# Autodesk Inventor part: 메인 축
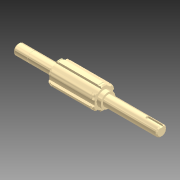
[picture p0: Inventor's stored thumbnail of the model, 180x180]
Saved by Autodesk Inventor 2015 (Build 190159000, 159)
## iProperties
Created: 2012-05
Part Number: 메인 축
Document SubType Name: 모델링
Designer: SeoGD™
Mass: 168.352 g
Surface Area: 72.5104 cm^2
Volume: 21.4461 cm^3
Density: 7.85 g/cm^3
Material: 강철, 연강
Appearance: 반연마
변환 표준: STEP AP214IS
파일 이름: C:\Users\SeoGD\Desktop\?쒗뿕\硫붿씤 異?.stp
전처리기: Build: 253, Release: 2010 SP1 - Date: Wed 07/29/2009
전송 단위: 밀리미터
불확실성: 0.01
Author: SeoGD™
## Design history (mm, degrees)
sketch "스케치1"
  geometry: L1 (-69.5, 0)-(69.5, 0); L2 (69.5, 0)-(69.5, 5); L3 (69.5, 5)-(55.5, 5); L4 (55.5, 5)-(55.5, 4.8); L5 (55.5, 4.8)-(54.35, 4.8); L6 (54.35, 4.8)-(54.35, 5); L7 (54.35, 5)-(30.5, 5); L8 (30.5, 5)-(30.5, 9); L9 (30.5, 9)-(-13.5, 9); L10 (-13.5, 9)-(-13.5, 7); L11 (-13.5, 7)-(-17.5, 7); L12 (-17.5, 7)-(-17.5, 5); L13 (-17.5, 5)-(-69.5, 5); L14 (-69.5, 5)-(-69.5, 0); 2 further points
  constraints: 28 end point, 9 parallel, 4 collinear, 2 perpendicular, 1 coincident, 1 horizontal, 1 midpoint
  dimensions: "d2" = 1.15 distance between parallel lines of L6 L4; "d3" = 10 diameter of L3 L1; "d4" = 9.6 diameter of L5 L1; "d6" = 44 distance between parallel lines of L10 L8; "d7" = 4 distance between parallel lines of L12 L10; "d8" = 14 diameter of L11 L1; "d9" = 18 diameter of L9 L1; "d33" = 52 distance from line of L12.end L14; "d37" = 39 distance between parallel lines of L8 L2; "d38" = 14 distance between parallel lines of L2 L4
revolve "회전1" sketch "스케치1" stored, may be unused: angle "d10" = 90 deg
sketch "스케치2"
  geometry: L1 (2.5, 10.712)-(2.5, 8.646); L2 (-2.5, 10.712)-(-2.5, 8.646); A1 r 9 centre (0, 0) between (2.5, 8.646) and (-2.5, 8.646) reference; A2 r 11 centre (0, 0) between (2.5, 10.712) and (-2.5, 10.712); 1 further point
  constraints: 4 end point, 4 point on circle, 2 parallel, 1 centre point, 1 coincident, 1 vertical
  dimensions: "d11" = 22 diameter of A2; "d12" = 5 distance between parallel lines of L1 L2
extrude "돌출1" join sketch "스케치2" stored distance "d13" = 10; taper "d14" = 0 deg
chamfer "모따기1" distance "d15" = 1; stored, may be unused: second distance "d16" = 2, angle "d17" = 45 deg
node "작업 평면1"
node "작업 평면2"
sketch "스케치3"
  geometry: L1 (2.5, 10.712)-(2.5, 10.198); L2 (-2.5, 10.712)-(-2.5, 10.198); A1 r 11 centre (0, 0) between (2.5, 10.712) and (-2.5, 10.712) reference; A2 r 10.5 centre (0, 0) between (2.5, 10.198) and (-2.5, 10.198); 1 further point
  constraints: 4 end point, 2 point on circle, 1 centre point, 1 coincident, 1 parallel, 1 vertical
  dimensions: "d19" = 21 diameter of A2
extrude "돌출2" cut sketch "스케치3" distance "d20" = 1.35; taper "d21" = 0 deg
node "작업 평면3"
sketch "스케치4"
  geometry: L1 (-26, -5)-(-26, 5) reference; L2 (-26, 1.5)-(-12.5, 1.5); L3 (-12.5, -1.5)-(-26, -1.5); A1 r 1.5 centre (-12.5, 0) between (-12.5, -1.5) and (-12.5, 1.5); 2 further points
  constraints: 4 end point, 2 perpendicular, 2 point on circle, 2 point on line, 2 tangent, 1 centre point, 1 horizontal alignment, 1 midpoint
  dimensions: "d25" = 3 distance between parallel lines of L3 L2; "d26" = 15 dimension on A1 L1
extrude "돌출3" cut sketch "스케치4" distance "d27" = 1.8; taper "d28" = 0 deg
chamfer "모따기2" distance "d29" = 1; stored, may be unused: second distance "d30" = 2, angle "d31" = 45 deg
node "솔리드1"
node "솔리드 본체"
node "곡면 본체"
mirror "대칭1"
pattern_circular "원형 패턴1" dims "d23" = 360 deg
node "솔리드2"
other parameters: "d18" = -1.65
